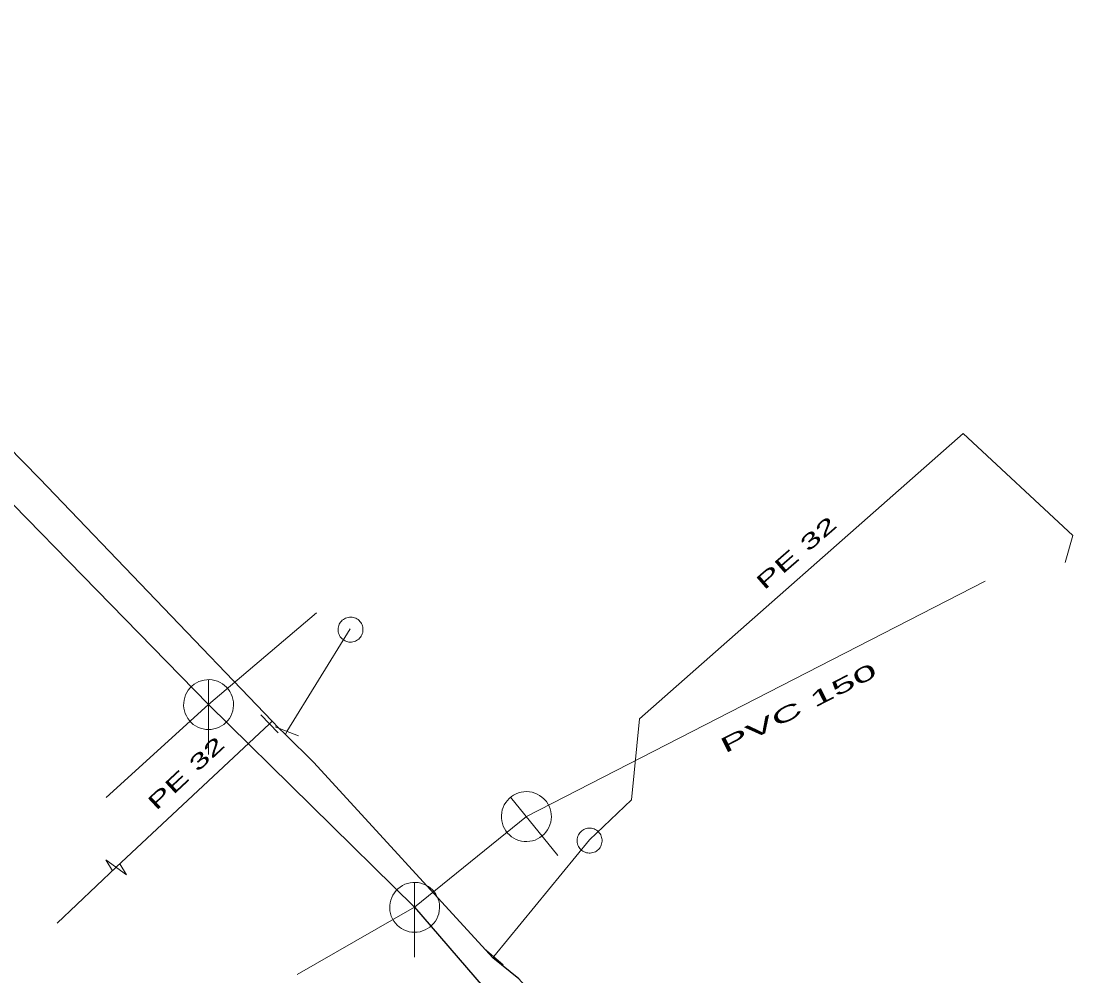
# Model space of a CAD drawing. Extents: x -809028 to -807737, y -990545 to -989489.
# Drawn here: x -808180.89 to -808138.76, y -989781.35 to -989743.11 of the extents above; entities that cross this region are included whole.
import ezdxf

# ---------------------------------------------------------------- set-up
doc = ezdxf.new("R2010")
doc.units = 0
doc.header["$LTSCALE"] = 0.32
for name, color, linetype, lineweight in [('1', 7, 'Continuous', 13), ('11', 7, 'Continuous', 13), ('13', 7, 'Continuous', 13), ('14', 7, 'Continuous', 25), ('17', 7, 'Continuous', 25), ('22', 7, 'Continuous', 13), ('23', 7, 'Continuous', 13), ('34', 7, 'Continuous', 13), ('47', 7, 'Continuous', 13)]:
    doc.layers.add(name, color=color, linetype=linetype, lineweight=lineweight)

msp = doc.modelspace()

# ---------------------------------------------------------------- linework, layer by layer
at = {"layer": '11'}
for p, q in [((-808142.283, -989765.537), (-808160.649, -989774.969)), ((-808169.05, -989766.809), (-808173.375, -989770.484)), ((-808177.48, -989774.21), (-808173.375, -989770.484)), ((-808160.649, -989774.969), (-808165.124, -989778.603)), ((-808169.829, -989781.3), (-808165.124, -989778.603))]:
    msp.add_line(p, q, dxfattribs=at)
at = {"layer": '13'}
for p, q in [((-808170.239, -989771.559), (-808167.699, -989767.449)), ((-808170.939, -989771.25), (-808177.079, -989777)), ((-808161.955, -989780.578), (-808158.12, -989775.899)), ((-808177.079, -989777), (-808179.441, -989779.238))]:
    msp.add_line(p, q, dxfattribs=at)
msp.add_lwpolyline([(-808158.12, -989775.899), (-808156.434, -989774.294), (-808156.125, -989771.052), (-808143.16, -989759.625), (-808138.761, -989763.717), (-808139.07, -989764.798)], dxfattribs=at)
at = {"layer": '14'}
msp.add_line((-808173.375, -989770.484), (-808165.124, -989778.603), dxfattribs=at)
at = {"layer": '14', "lineweight": 13}
for p, q in [((-808170.835, -989771.151), (-808170.939, -989771.25)), ((-808170.289, -989771.688), (-808170.239, -989771.559)), ((-808161.989, -989780.62), (-808161.955, -989780.578))]:
    msp.add_line(p, q, dxfattribs=at)
at = {"layer": '14'}
for points in [[(-808200.125, -989743.107), (-808190.092, -989753.39), (-808186.248, -989757.316), (-808173.375, -989770.484)], [(-808165.124, -989778.603), (-808151.375, -989794.546), (-808144.42, -989802.57)]]:
    msp.add_lwpolyline(points, dxfattribs=at)
at = {"layer": '17'}
msp.add_lwpolyline([(-808145.339, -989799.479), (-808145.752, -989798.908), (-808153.039, -989790.37), (-808160.949, -989781.469), (-808161.989, -989780.62), (-808169.16, -989772.8), (-808170.289, -989771.688), (-808170.581, -989771.418), (-808170.835, -989771.151), (-808180.144, -989761.434), (-808185.94, -989755.53)], dxfattribs=at)
at = {"layer": '22'}
for p, q in [((-808173.375, -989772.484), (-808173.374, -989769.484)), ((-808159.387, -989776.521), (-808161.279, -989774.193)), ((-808165.124, -989780.603), (-808165.123, -989777.603))]:
    msp.add_line(p, q, dxfattribs=at)
for points in [[(-808172.375, -989770.484), (-808172.38, -989770.375), (-808172.398, -989770.267), (-808172.428, -989770.161), (-808172.468, -989770.06), (-808172.52, -989769.963), (-808172.582, -989769.873), (-808172.654, -989769.79), (-808172.734, -989769.716), (-808172.822, -989769.65), (-808172.916, -989769.595), (-808173.016, -989769.55), (-808173.121, -989769.517), (-808173.228, -989769.495), (-808173.337, -989769.485), (-808173.447, -989769.487), (-808173.555, -989769.501), (-808173.662, -989769.526), (-808173.765, -989769.563), (-808173.863, -989769.612), (-808173.955, -989769.67), (-808174.041, -989769.739), (-808174.118, -989769.816), (-808174.187, -989769.902), (-808174.246, -989769.994), (-808174.294, -989770.092), (-808174.331, -989770.195), (-808174.357, -989770.302), (-808174.371, -989770.41), (-808174.374, -989770.52), (-808174.364, -989770.629), (-808174.343, -989770.736), (-808174.309, -989770.84), (-808174.265, -989770.94), (-808174.21, -989771.035), (-808174.144, -989771.123), (-808174.07, -989771.203), (-808173.987, -989771.275), (-808173.897, -989771.337), (-808173.801, -989771.389), (-808173.699, -989771.43), (-808173.594, -989771.46), (-808173.486, -989771.478), (-808173.376, -989771.484), (-808173.267, -989771.478), (-808173.159, -989771.46), (-808173.054, -989771.431), (-808172.952, -989771.39), (-808172.855, -989771.338), (-808172.765, -989771.276), (-808172.682, -989771.205), (-808172.607, -989771.125), (-808172.542, -989771.037), (-808172.486, -989770.943), (-808172.442, -989770.843), (-808172.408, -989770.739), (-808172.386, -989770.631), (-808172.376, -989770.522)], [(-808159.872, -989774.338), (-808159.945, -989774.258), (-808160.027, -989774.185), (-808160.118, -989774.122), (-808160.212, -989774.069), (-808160.314, -989774.026), (-808160.419, -989773.995), (-808160.527, -989773.976), (-808160.636, -989773.969), (-808160.746, -989773.974), (-808160.853, -989773.99), (-808160.959, -989774.018), (-808161.061, -989774.059), (-808161.158, -989774.109), (-808161.249, -989774.17), (-808161.333, -989774.241), (-808161.408, -989774.32), (-808161.476, -989774.407), (-808161.532, -989774.501), (-808161.578, -989774.6), (-808161.612, -989774.703), (-808161.636, -989774.811), (-808161.647, -989774.919), (-808161.646, -989775.03), (-808161.634, -989775.138), (-808161.609, -989775.245), (-808161.573, -989775.348), (-808161.526, -989775.447), (-808161.469, -989775.54), (-808161.401, -989775.627), (-808161.324, -989775.705), (-808161.241, -989775.775), (-808161.149, -989775.834), (-808161.052, -989775.884), (-808160.949, -989775.923), (-808160.842, -989775.95), (-808160.734, -989775.965), (-808160.625, -989775.969), (-808160.516, -989775.96), (-808160.408, -989775.94), (-808160.303, -989775.907), (-808160.203, -989775.865), (-808160.108, -989775.81), (-808160.018, -989775.746), (-808159.938, -989775.672), (-808159.865, -989775.59), (-808159.802, -989775.502), (-808159.749, -989775.405), (-808159.706, -989775.304), (-808159.675, -989775.199), (-808159.656, -989775.092), (-808159.648, -989774.982), (-808159.653, -989774.873), (-808159.669, -989774.765), (-808159.698, -989774.659), (-808159.737, -989774.557), (-808159.788, -989774.459), (-808159.849, -989774.369)], [(-808164.124, -989778.603), (-808164.129, -989778.494), (-808164.147, -989778.386), (-808164.177, -989778.28), (-808164.217, -989778.179), (-808164.269, -989778.082), (-808164.331, -989777.992), (-808164.403, -989777.909), (-808164.483, -989777.835), (-808164.571, -989777.769), (-808164.665, -989777.714), (-808164.765, -989777.669), (-808164.87, -989777.636), (-808164.977, -989777.614), (-808165.086, -989777.604), (-808165.196, -989777.606), (-808165.304, -989777.62), (-808165.411, -989777.645), (-808165.514, -989777.682), (-808165.612, -989777.731), (-808165.704, -989777.789), (-808165.79, -989777.858), (-808165.867, -989777.935), (-808165.936, -989778.021), (-808165.995, -989778.113), (-808166.043, -989778.211), (-808166.08, -989778.314), (-808166.106, -989778.421), (-808166.12, -989778.529), (-808166.123, -989778.639), (-808166.113, -989778.748), (-808166.092, -989778.855), (-808166.058, -989778.959), (-808166.014, -989779.059), (-808165.959, -989779.154), (-808165.893, -989779.242), (-808165.819, -989779.322), (-808165.736, -989779.394), (-808165.646, -989779.456), (-808165.55, -989779.508), (-808165.448, -989779.549), (-808165.343, -989779.579), (-808165.235, -989779.597), (-808165.125, -989779.603), (-808165.016, -989779.597), (-808164.908, -989779.579), (-808164.803, -989779.55), (-808164.701, -989779.509), (-808164.604, -989779.457), (-808164.514, -989779.395), (-808164.431, -989779.324), (-808164.356, -989779.244), (-808164.291, -989779.156), (-808164.235, -989779.062), (-808164.191, -989778.962), (-808164.157, -989778.858), (-808164.135, -989778.75), (-808164.125, -989778.641)]]:
    msp.add_lwpolyline(points, close=True, dxfattribs=at)
at = {"layer": '23'}
for points in [[(-808167.433, -989767.052), (-808167.48, -989767.027), (-808167.528, -989767.007), (-808167.578, -989766.994), (-808167.63, -989766.984), (-808167.681, -989766.981), (-808167.735, -989766.983), (-808167.786, -989766.99), (-808167.836, -989767.003), (-808167.886, -989767.02), (-808167.933, -989767.043), (-808167.978, -989767.07), (-808168.019, -989767.103), (-808168.057, -989767.139), (-808168.09, -989767.179), (-808168.119, -989767.221), (-808168.144, -989767.269), (-808168.164, -989767.316), (-808168.178, -989767.368), (-808168.188, -989767.418), (-808168.192, -989767.47), (-808168.189, -989767.524), (-808168.182, -989767.575), (-808168.169, -989767.627), (-808168.152, -989767.676), (-808168.129, -989767.722), (-808168.1, -989767.767), (-808168.069, -989767.807), (-808168.032, -989767.845), (-808167.992, -989767.878), (-808167.949, -989767.908), (-808167.903, -989767.933), (-808167.854, -989767.953), (-808167.804, -989767.968), (-808167.753, -989767.977), (-808167.701, -989767.979), (-808167.649, -989767.978), (-808167.597, -989767.971), (-808167.545, -989767.958), (-808167.496, -989767.94)], [(-808167.496, -989767.94), (-808167.45, -989767.918), (-808167.405, -989767.89), (-808167.364, -989767.859), (-808167.326, -989767.821), (-808167.293, -989767.781), (-808167.263, -989767.738), (-808167.24, -989767.692), (-808167.219, -989767.644), (-808167.204, -989767.593), (-808167.196, -989767.542), (-808167.192, -989767.489), (-808167.193, -989767.438), (-808167.202, -989767.385), (-808167.213, -989767.335), (-808167.231, -989767.286), (-808167.254, -989767.238), (-808167.282, -989767.194), (-808167.314, -989767.152), (-808167.351, -989767.115), (-808167.39, -989767.082), (-808167.433, -989767.052), (-808167.48, -989767.027), (-808167.528, -989767.007), (-808167.578, -989766.994), (-808167.63, -989766.984), (-808167.681, -989766.981), (-808167.735, -989766.983), (-808167.786, -989766.99), (-808167.836, -989767.003), (-808167.886, -989767.02), (-808167.933, -989767.043), (-808167.978, -989767.07), (-808168.019, -989767.103), (-808168.057, -989767.139), (-808168.09, -989767.179), (-808168.119, -989767.221), (-808168.144, -989767.269), (-808168.164, -989767.316), (-808168.178, -989767.368)], [(-808168.178, -989767.368), (-808168.188, -989767.418), (-808168.192, -989767.47), (-808168.189, -989767.524), (-808168.182, -989767.575), (-808168.169, -989767.627), (-808168.152, -989767.676), (-808168.129, -989767.722), (-808168.1, -989767.767), (-808168.069, -989767.807), (-808168.032, -989767.845), (-808167.992, -989767.878), (-808167.949, -989767.908), (-808167.903, -989767.933), (-808167.854, -989767.953), (-808167.804, -989767.968), (-808167.753, -989767.977), (-808167.701, -989767.979), (-808167.649, -989767.978), (-808167.597, -989767.971), (-808167.545, -989767.958), (-808167.496, -989767.94), (-808167.45, -989767.918), (-808167.405, -989767.89), (-808167.364, -989767.859), (-808167.326, -989767.821), (-808167.293, -989767.781), (-808167.263, -989767.738), (-808167.24, -989767.692), (-808167.219, -989767.644), (-808167.204, -989767.593), (-808167.196, -989767.542), (-808167.192, -989767.489), (-808167.193, -989767.438), (-808167.202, -989767.385), (-808167.213, -989767.335), (-808167.231, -989767.286), (-808167.254, -989767.238), (-808167.282, -989767.194), (-808167.314, -989767.152)], [(-808167.314, -989767.152), (-808167.351, -989767.115), (-808167.39, -989767.082), (-808167.433, -989767.052)], [(-808157.804, -989775.541), (-808157.846, -989775.509), (-808157.892, -989775.483), (-808157.94, -989775.464), (-808157.99, -989775.448), (-808158.04, -989775.437), (-808158.094, -989775.432), (-808158.145, -989775.432), (-808158.197, -989775.438), (-808158.248, -989775.449), (-808158.298, -989775.465), (-808158.346, -989775.486), (-808158.392, -989775.514), (-808158.433, -989775.544), (-808158.471, -989775.579), (-808158.507, -989775.617), (-808158.538, -989775.662), (-808158.563, -989775.705), (-808158.585, -989775.755), (-808158.6, -989775.803), (-808158.612, -989775.855), (-808158.616, -989775.908), (-808158.615, -989775.96), (-808158.609, -989776.013), (-808158.599, -989776.064), (-808158.583, -989776.112), (-808158.56, -989776.161), (-808158.534, -989776.205), (-808158.503, -989776.247), (-808158.467, -989776.286), (-808158.429, -989776.321), (-808158.387, -989776.352), (-808158.341, -989776.378), (-808158.293, -989776.399), (-808158.244, -989776.415), (-808158.193, -989776.424), (-808158.14, -989776.43), (-808158.088, -989776.43), (-808158.035, -989776.424), (-808157.984, -989776.413)], [(-808158.585, -989775.755), (-808158.6, -989775.803), (-808158.612, -989775.855), (-808158.616, -989775.908), (-808158.615, -989775.96), (-808158.609, -989776.013), (-808158.599, -989776.064), (-808158.583, -989776.112), (-808158.56, -989776.161), (-808158.534, -989776.205), (-808158.503, -989776.247), (-808158.467, -989776.286), (-808158.429, -989776.321), (-808158.387, -989776.352), (-808158.341, -989776.378), (-808158.293, -989776.399), (-808158.244, -989776.415), (-808158.193, -989776.424), (-808158.14, -989776.43), (-808158.088, -989776.43), (-808158.035, -989776.424), (-808157.984, -989776.413), (-808157.935, -989776.397), (-808157.887, -989776.375), (-808157.842, -989776.35), (-808157.8, -989776.317), (-808157.762, -989776.282), (-808157.727, -989776.244), (-808157.697, -989776.201), (-808157.67, -989776.156), (-808157.649, -989776.107), (-808157.634, -989776.058), (-808157.622, -989776.006), (-808157.617, -989775.955), (-808157.619, -989775.902), (-808157.623, -989775.85), (-808157.634, -989775.8), (-808157.651, -989775.749), (-808157.673, -989775.701), (-808157.699, -989775.656)], [(-808157.984, -989776.413), (-808157.935, -989776.397), (-808157.887, -989776.375), (-808157.842, -989776.35), (-808157.8, -989776.317), (-808157.762, -989776.282), (-808157.727, -989776.244), (-808157.697, -989776.201), (-808157.67, -989776.156), (-808157.649, -989776.107), (-808157.634, -989776.058), (-808157.622, -989776.006), (-808157.617, -989775.955), (-808157.619, -989775.902), (-808157.623, -989775.85), (-808157.634, -989775.8), (-808157.651, -989775.749), (-808157.673, -989775.701), (-808157.699, -989775.656), (-808157.731, -989775.615), (-808157.765, -989775.576), (-808157.804, -989775.541), (-808157.846, -989775.509), (-808157.892, -989775.483), (-808157.94, -989775.464), (-808157.99, -989775.448), (-808158.04, -989775.437), (-808158.094, -989775.432), (-808158.145, -989775.432), (-808158.197, -989775.438), (-808158.248, -989775.449), (-808158.298, -989775.465), (-808158.346, -989775.486), (-808158.392, -989775.514), (-808158.433, -989775.544), (-808158.471, -989775.579), (-808158.507, -989775.617), (-808158.538, -989775.662), (-808158.563, -989775.705), (-808158.585, -989775.755)], [(-808157.699, -989775.656), (-808157.731, -989775.615), (-808157.765, -989775.576), (-808157.804, -989775.541)]]:
    msp.add_lwpolyline(points, dxfattribs=at)
at = {"layer": '34'}
for p, q in [((-808171.284, -989770.888), (-808170.594, -989771.612)), ((-808170.705, -989771.378), (-808169.772, -989771.74)), ((-808162.334, -989780.252), (-808161.575, -989780.903))]:
    msp.add_line(p, q, dxfattribs=at)
at = {"layer": '47'}
msp.add_line((-808176.665, -989777.297), (-808176.932, -989776.862), dxfattribs=at)
msp.add_lwpolyline([(-808176.665, -989777.297), (-808177.492, -989776.702), (-808177.225, -989777.137)], dxfattribs=at)

# ---------------------------------------------------------------- texts
at = {"layer": '1'}
for s, rotation, width, p in [('PE 32 ', 41, 1.8, (-808151.126, -989765.923)), ('PVC 150 ', 27, 2.15, (-808152.697, -989772.45)), ('PE 32 ', 43, 1.75, (-808175.473, -989774.754))]:
    msp.add_text(s, height=0.6, rotation=rotation, dxfattribs=dict(at, width=width)).set_placement(p)

doc.saveas('drawing.dxf')
